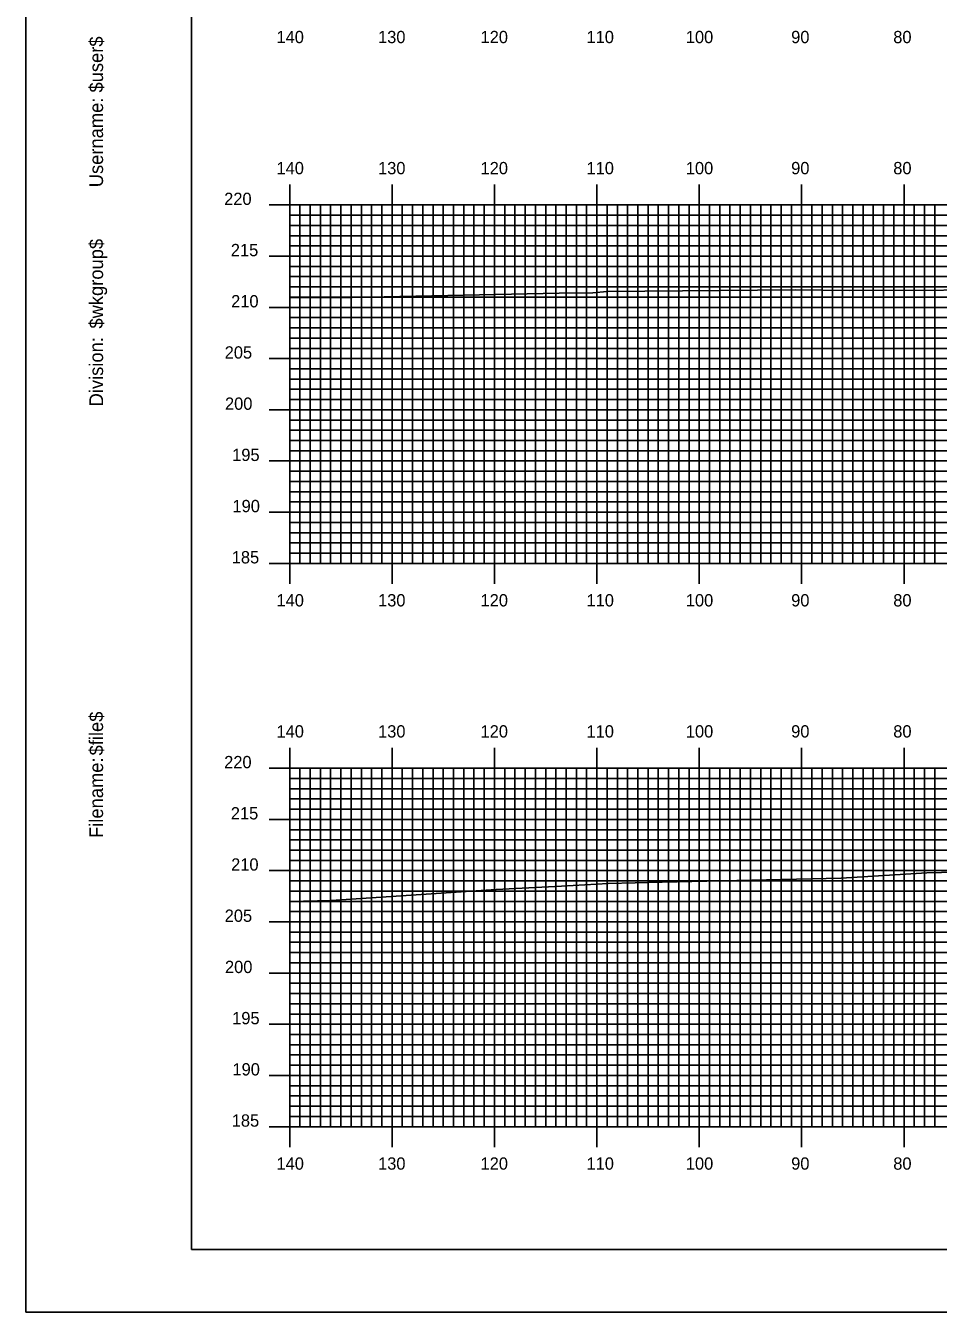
# Model space of a CAD drawing. Extents: x 1799962 to 1800305, y 442591 to 442811.
# Drawn here: x 1799961.7 to 1800050.9, y 442590.5 to 442716.2 of the extents above; entities that cross this region are included whole.
import ezdxf

# ---------------------------------------------------------------- set-up
doc = ezdxf.new("R2010")
doc.units = 0
for name, color, linetype in [('BORDER', 7, 'Continuous'), ('H_V ANNOTATION', 7, 'Continuous'), ('MAJOR', 7, 'Continuous'), ('MINOR', 7, 'Continuous'), ('PLOT BOUNDARY', 7, 'Continuous'), ('S_Roadway_Centerline', 7, 'Continuous')]:
    doc.layers.add(name, color=color, linetype=linetype)

msp = doc.modelspace()

# ---------------------------------------------------------------- linework, layer by layer
at = {"layer": 'BORDER'}
msp.add_lwpolyline([(1799977.92, 442596.67), (1800297.92, 442596.67), (1800297.92, 442806.67), (1799977.92, 442806.67)], close=True, dxfattribs=at)
at = {"layer": 'MAJOR'}
for p, q in [((1799987.52, 442700.67), (1799987.52, 442698.67)), ((1799997.52, 442700.67), (1799997.52, 442698.67)), ((1800007.52, 442700.67), (1800007.52, 442698.67)), ((1800017.52, 442700.67), (1800017.52, 442698.67)), ((1800027.52, 442700.67), (1800027.52, 442698.67)), ((1800037.52, 442700.67), (1800037.52, 442698.67)), ((1800047.52, 442700.67), (1800047.52, 442698.67)), ((1799985.52, 442698.67), (1799987.52, 442698.67)), ((1799987.52, 442698.67), (1800267.52, 442698.67)), ((1799987.52, 442663.67), (1799987.52, 442698.67)), ((1799987.52, 442663.67), (1799987.52, 442698.67)), ((1799987.52, 442698.67), (1800267.52, 442698.67)), ((1799997.52, 442663.67), (1799997.52, 442698.67)), ((1800007.52, 442663.67), (1800007.52, 442698.67)), ((1800017.52, 442663.67), (1800017.52, 442698.67)), ((1800027.52, 442663.67), (1800027.52, 442698.67)), ((1800037.52, 442663.67), (1800037.52, 442698.67)), ((1800047.52, 442663.67), (1800047.52, 442698.67)), ((1799985.52, 442693.67), (1799987.52, 442693.67)), ((1799987.52, 442693.67), (1800267.52, 442693.67)), ((1799985.52, 442688.67), (1799987.52, 442688.67)), ((1799987.52, 442688.67), (1800267.52, 442688.67)), ((1799985.52, 442683.67), (1799987.52, 442683.67)), ((1799987.52, 442683.67), (1800267.52, 442683.67)), ((1799985.52, 442678.67), (1799987.52, 442678.67)), ((1799987.52, 442678.67), (1800267.52, 442678.67)), ((1799985.52, 442673.67), (1799987.52, 442673.67)), ((1799987.52, 442673.67), (1800267.52, 442673.67)), ((1799985.52, 442668.67), (1799987.52, 442668.67)), ((1799987.52, 442668.67), (1800267.52, 442668.67)), ((1799985.52, 442663.67), (1799987.52, 442663.67)), ((1799987.52, 442663.67), (1800267.52, 442663.67)), ((1799987.52, 442663.67), (1800267.52, 442663.67)), ((1799987.52, 442661.66), (1799987.52, 442663.67)), ((1799997.52, 442661.66), (1799997.52, 442663.67)), ((1800007.52, 442661.66), (1800007.52, 442663.67)), ((1800017.52, 442661.66), (1800017.52, 442663.67)), ((1800027.52, 442661.66), (1800027.52, 442663.67)), ((1800037.52, 442661.66), (1800037.52, 442663.67)), ((1800047.52, 442661.66), (1800047.52, 442663.67)), ((1799987.52, 442645.67), (1799987.52, 442643.67)), ((1799997.52, 442645.67), (1799997.52, 442643.67)), ((1800007.52, 442645.67), (1800007.52, 442643.67)), ((1800017.52, 442645.67), (1800017.52, 442643.67)), ((1800027.52, 442645.67), (1800027.52, 442643.67)), ((1800037.52, 442645.67), (1800037.52, 442643.67)), ((1800047.52, 442645.67), (1800047.52, 442643.67)), ((1799985.52, 442643.67), (1799987.52, 442643.67)), ((1799987.52, 442643.67), (1800267.52, 442643.67)), ((1799987.52, 442608.67), (1799987.52, 442643.67)), ((1799987.52, 442608.67), (1799987.52, 442643.67)), ((1799987.52, 442643.67), (1800267.52, 442643.67)), ((1799997.52, 442608.67), (1799997.52, 442643.67)), ((1800007.52, 442608.67), (1800007.52, 442643.67)), ((1800017.52, 442608.67), (1800017.52, 442643.67)), ((1800027.52, 442608.67), (1800027.52, 442643.67)), ((1800037.52, 442608.67), (1800037.52, 442643.67)), ((1800047.52, 442608.67), (1800047.52, 442643.67)), ((1799985.52, 442638.67), (1799987.52, 442638.67)), ((1799987.52, 442638.67), (1800267.52, 442638.67)), ((1799985.52, 442633.67), (1799987.52, 442633.67)), ((1799987.52, 442633.67), (1800267.52, 442633.67)), ((1799985.52, 442628.67), (1799987.52, 442628.67)), ((1799987.52, 442628.67), (1800267.52, 442628.67)), ((1799985.52, 442623.67), (1799987.52, 442623.67)), ((1799987.52, 442623.67), (1800267.52, 442623.67)), ((1799985.52, 442618.67), (1799987.52, 442618.67)), ((1799987.52, 442618.67), (1800267.52, 442618.67)), ((1799985.52, 442613.67), (1799987.52, 442613.67)), ((1799987.52, 442613.67), (1800267.52, 442613.67)), ((1799985.52, 442608.67), (1799987.52, 442608.67)), ((1799987.52, 442608.67), (1800267.52, 442608.67)), ((1799987.52, 442608.67), (1800267.52, 442608.67)), ((1799987.52, 442606.66), (1799987.52, 442608.67)), ((1799997.52, 442606.66), (1799997.52, 442608.67)), ((1800007.52, 442606.66), (1800007.52, 442608.67)), ((1800017.52, 442606.66), (1800017.52, 442608.67)), ((1800027.52, 442606.66), (1800027.52, 442608.67)), ((1800037.52, 442606.66), (1800037.52, 442608.67)), ((1800047.52, 442606.66), (1800047.52, 442608.67))]:
    msp.add_line(p, q, dxfattribs=at)
at = {"layer": 'MINOR'}
for p, q in [((1799988.52, 442663.67), (1799988.52, 442698.67)), ((1799989.52, 442663.67), (1799989.52, 442698.67)), ((1799990.52, 442663.67), (1799990.52, 442698.67)), ((1799991.52, 442663.67), (1799991.52, 442698.67)), ((1799992.52, 442663.67), (1799992.52, 442698.67)), ((1799993.52, 442663.67), (1799993.52, 442698.67)), ((1799994.52, 442663.67), (1799994.52, 442698.67)), ((1799995.52, 442663.67), (1799995.52, 442698.67)), ((1799996.52, 442663.67), (1799996.52, 442698.67)), ((1799998.52, 442663.67), (1799998.52, 442698.67)), ((1799999.52, 442663.67), (1799999.52, 442698.67)), ((1800000.52, 442663.67), (1800000.52, 442698.67)), ((1800001.52, 442663.67), (1800001.52, 442698.67)), ((1800002.52, 442663.67), (1800002.52, 442698.67)), ((1800003.52, 442663.67), (1800003.52, 442698.67)), ((1800004.52, 442663.67), (1800004.52, 442698.67)), ((1800005.52, 442663.67), (1800005.52, 442698.67)), ((1800006.52, 442663.67), (1800006.52, 442698.67)), ((1800008.52, 442663.67), (1800008.52, 442698.67)), ((1800009.52, 442663.67), (1800009.52, 442698.67)), ((1800010.52, 442663.67), (1800010.52, 442698.67)), ((1800011.52, 442663.67), (1800011.52, 442698.67)), ((1800012.52, 442663.67), (1800012.52, 442698.67)), ((1800013.52, 442663.67), (1800013.52, 442698.67)), ((1800014.52, 442663.67), (1800014.52, 442698.67)), ((1800015.52, 442663.67), (1800015.52, 442698.67)), ((1800016.52, 442663.67), (1800016.52, 442698.67)), ((1800018.52, 442663.67), (1800018.52, 442698.67)), ((1800019.52, 442663.67), (1800019.52, 442698.67)), ((1800020.52, 442663.67), (1800020.52, 442698.67)), ((1800021.52, 442663.67), (1800021.52, 442698.67)), ((1800022.52, 442663.67), (1800022.52, 442698.67)), ((1800023.52, 442663.67), (1800023.52, 442698.67)), ((1800024.52, 442663.67), (1800024.52, 442698.67)), ((1800025.52, 442663.67), (1800025.52, 442698.67)), ((1800026.52, 442663.67), (1800026.52, 442698.67)), ((1800028.52, 442663.67), (1800028.52, 442698.67)), ((1800029.52, 442663.67), (1800029.52, 442698.67)), ((1800030.52, 442663.67), (1800030.52, 442698.67)), ((1800031.52, 442663.67), (1800031.52, 442698.67)), ((1800032.52, 442663.67), (1800032.52, 442698.67)), ((1800033.52, 442663.67), (1800033.52, 442698.67)), ((1800034.52, 442663.67), (1800034.52, 442698.67)), ((1800035.52, 442663.67), (1800035.52, 442698.67)), ((1800036.52, 442663.67), (1800036.52, 442698.67)), ((1800038.52, 442663.67), (1800038.52, 442698.67)), ((1800039.52, 442663.67), (1800039.52, 442698.67)), ((1800040.52, 442663.67), (1800040.52, 442698.67)), ((1800041.52, 442663.67), (1800041.52, 442698.67)), ((1800042.52, 442663.67), (1800042.52, 442698.67)), ((1800043.52, 442663.67), (1800043.52, 442698.67)), ((1800044.52, 442663.67), (1800044.52, 442698.67)), ((1800045.52, 442663.67), (1800045.52, 442698.67)), ((1800046.52, 442663.67), (1800046.52, 442698.67)), ((1800048.52, 442663.67), (1800048.52, 442698.67)), ((1800049.52, 442663.67), (1800049.52, 442698.67)), ((1800050.52, 442663.67), (1800050.52, 442698.67)), ((1799987.52, 442697.67), (1800267.52, 442697.67)), ((1799987.52, 442697.67), (1799989.53, 442697.67)), ((1799987.52, 442696.67), (1800267.52, 442696.67)), ((1799987.52, 442696.67), (1799989.53, 442696.67)), ((1799987.52, 442695.67), (1800267.52, 442695.67)), ((1799987.52, 442695.67), (1799989.53, 442695.67)), ((1799987.52, 442694.67), (1800267.52, 442694.67)), ((1799987.52, 442694.67), (1799989.53, 442694.67)), ((1799987.52, 442692.67), (1800267.52, 442692.67)), ((1799987.52, 442692.67), (1799989.53, 442692.67)), ((1799987.52, 442691.67), (1800267.52, 442691.67)), ((1799987.52, 442691.67), (1799989.53, 442691.67)), ((1799987.52, 442690.67), (1800267.52, 442690.67)), ((1799987.52, 442690.67), (1799989.53, 442690.67)), ((1799987.52, 442689.67), (1800267.52, 442689.67)), ((1799987.52, 442689.67), (1799989.53, 442689.67)), ((1799987.52, 442687.67), (1800267.52, 442687.67)), ((1799987.52, 442687.67), (1799989.53, 442687.67)), ((1799987.52, 442686.67), (1800267.52, 442686.67)), ((1799987.52, 442686.67), (1799989.53, 442686.67)), ((1799987.52, 442685.67), (1800267.52, 442685.67)), ((1799987.52, 442685.67), (1799989.53, 442685.67)), ((1799987.52, 442684.67), (1800267.52, 442684.67)), ((1799987.52, 442684.67), (1799989.53, 442684.67)), ((1799987.52, 442682.67), (1800267.52, 442682.67)), ((1799987.52, 442682.67), (1799989.53, 442682.67)), ((1799987.52, 442681.67), (1800267.52, 442681.67)), ((1799987.52, 442681.67), (1799989.53, 442681.67)), ((1799987.52, 442680.67), (1800267.52, 442680.67)), ((1799987.52, 442680.67), (1799989.53, 442680.67)), ((1799987.52, 442679.67), (1800267.52, 442679.67)), ((1799987.52, 442679.67), (1799989.53, 442679.67)), ((1799987.52, 442677.67), (1800267.52, 442677.67)), ((1799987.52, 442677.67), (1799989.53, 442677.67)), ((1799987.52, 442676.67), (1800267.52, 442676.67)), ((1799987.52, 442676.67), (1799989.53, 442676.67)), ((1799987.52, 442675.67), (1800267.52, 442675.67)), ((1799987.52, 442675.67), (1799989.53, 442675.67)), ((1799987.52, 442674.67), (1800267.52, 442674.67)), ((1799987.52, 442674.67), (1799989.53, 442674.67)), ((1799987.52, 442672.67), (1800267.52, 442672.67)), ((1799987.52, 442672.67), (1799989.53, 442672.67)), ((1799987.52, 442671.67), (1800267.52, 442671.67)), ((1799987.52, 442671.67), (1799989.53, 442671.67)), ((1799987.52, 442670.67), (1800267.52, 442670.67)), ((1799987.52, 442670.67), (1799989.53, 442670.67)), ((1799987.52, 442669.67), (1800267.52, 442669.67)), ((1799987.52, 442669.67), (1799989.53, 442669.67)), ((1799987.52, 442667.67), (1800267.52, 442667.67)), ((1799987.52, 442667.67), (1799989.53, 442667.67)), ((1799987.52, 442666.67), (1800267.52, 442666.67)), ((1799987.52, 442666.67), (1799989.53, 442666.67)), ((1799987.52, 442665.67), (1800267.52, 442665.67)), ((1799987.52, 442665.67), (1799989.53, 442665.67)), ((1799987.52, 442664.67), (1800267.52, 442664.67)), ((1799987.52, 442664.67), (1799989.53, 442664.67)), ((1799988.52, 442608.67), (1799988.52, 442643.67)), ((1799989.52, 442608.67), (1799989.52, 442643.67)), ((1799990.52, 442608.67), (1799990.52, 442643.67)), ((1799991.52, 442608.67), (1799991.52, 442643.67)), ((1799992.52, 442608.67), (1799992.52, 442643.67)), ((1799993.52, 442608.67), (1799993.52, 442643.67)), ((1799994.52, 442608.67), (1799994.52, 442643.67)), ((1799995.52, 442608.67), (1799995.52, 442643.67)), ((1799996.52, 442608.67), (1799996.52, 442643.67)), ((1799998.52, 442608.67), (1799998.52, 442643.67)), ((1799999.52, 442608.67), (1799999.52, 442643.67)), ((1800000.52, 442608.67), (1800000.52, 442643.67)), ((1800001.52, 442608.67), (1800001.52, 442643.67)), ((1800002.52, 442608.67), (1800002.52, 442643.67)), ((1800003.52, 442608.67), (1800003.52, 442643.67)), ((1800004.52, 442608.67), (1800004.52, 442643.67)), ((1800005.52, 442608.67), (1800005.52, 442643.67)), ((1800006.52, 442608.67), (1800006.52, 442643.67)), ((1800008.52, 442608.67), (1800008.52, 442643.67)), ((1800009.52, 442608.67), (1800009.52, 442643.67)), ((1800010.52, 442608.67), (1800010.52, 442643.67)), ((1800011.52, 442608.67), (1800011.52, 442643.67)), ((1800012.52, 442608.67), (1800012.52, 442643.67)), ((1800013.52, 442608.67), (1800013.52, 442643.67)), ((1800014.52, 442608.67), (1800014.52, 442643.67)), ((1800015.52, 442608.67), (1800015.52, 442643.67)), ((1800016.52, 442608.67), (1800016.52, 442643.67)), ((1800018.52, 442608.67), (1800018.52, 442643.67)), ((1800019.52, 442608.67), (1800019.52, 442643.67)), ((1800020.52, 442608.67), (1800020.52, 442643.67)), ((1800021.52, 442608.67), (1800021.52, 442643.67)), ((1800022.52, 442608.67), (1800022.52, 442643.67)), ((1800023.52, 442608.67), (1800023.52, 442643.67)), ((1800024.52, 442608.67), (1800024.52, 442643.67)), ((1800025.52, 442608.67), (1800025.52, 442643.67)), ((1800026.52, 442608.67), (1800026.52, 442643.67)), ((1800028.52, 442608.67), (1800028.52, 442643.67)), ((1800029.52, 442608.67), (1800029.52, 442643.67)), ((1800030.52, 442608.67), (1800030.52, 442643.67)), ((1800031.52, 442608.67), (1800031.52, 442643.67)), ((1800032.52, 442608.67), (1800032.52, 442643.67)), ((1800033.52, 442608.67), (1800033.52, 442643.67)), ((1800034.52, 442608.67), (1800034.52, 442643.67)), ((1800035.52, 442608.67), (1800035.52, 442643.67)), ((1800036.52, 442608.67), (1800036.52, 442643.67)), ((1800038.52, 442608.67), (1800038.52, 442643.67)), ((1800039.52, 442608.67), (1800039.52, 442643.67)), ((1800040.52, 442608.67), (1800040.52, 442643.67)), ((1800041.52, 442608.67), (1800041.52, 442643.67)), ((1800042.52, 442608.67), (1800042.52, 442643.67)), ((1800043.52, 442608.67), (1800043.52, 442643.67)), ((1800044.52, 442608.67), (1800044.52, 442643.67)), ((1800045.52, 442608.67), (1800045.52, 442643.67)), ((1800046.52, 442608.67), (1800046.52, 442643.67)), ((1800048.52, 442608.67), (1800048.52, 442643.67)), ((1800049.52, 442608.67), (1800049.52, 442643.67)), ((1800050.52, 442608.67), (1800050.52, 442643.67)), ((1799987.52, 442642.67), (1800267.52, 442642.67)), ((1799987.52, 442642.67), (1799989.53, 442642.67)), ((1799987.52, 442641.67), (1800267.52, 442641.67)), ((1799987.52, 442641.67), (1799989.53, 442641.67)), ((1799987.52, 442640.67), (1800267.52, 442640.67)), ((1799987.52, 442640.67), (1799989.53, 442640.67)), ((1799987.52, 442639.67), (1800267.52, 442639.67)), ((1799987.52, 442639.67), (1799989.53, 442639.67)), ((1799987.52, 442637.67), (1800267.52, 442637.67)), ((1799987.52, 442637.67), (1799989.53, 442637.67)), ((1799987.52, 442636.67), (1800267.52, 442636.67)), ((1799987.52, 442636.67), (1799989.53, 442636.67)), ((1799987.52, 442635.67), (1800267.52, 442635.67)), ((1799987.52, 442635.67), (1799989.53, 442635.67)), ((1799987.52, 442634.67), (1800267.52, 442634.67)), ((1799987.52, 442634.67), (1799989.53, 442634.67)), ((1799987.52, 442632.67), (1800267.52, 442632.67)), ((1799987.52, 442632.67), (1799989.53, 442632.67)), ((1799987.52, 442631.67), (1800267.52, 442631.67)), ((1799987.52, 442631.67), (1799989.53, 442631.67)), ((1799987.52, 442630.67), (1800267.52, 442630.67)), ((1799987.52, 442630.67), (1799989.53, 442630.67)), ((1799987.52, 442629.67), (1800267.52, 442629.67)), ((1799987.52, 442629.67), (1799989.53, 442629.67)), ((1799987.52, 442627.67), (1800267.52, 442627.67)), ((1799987.52, 442627.67), (1799989.53, 442627.67)), ((1799987.52, 442626.67), (1800267.52, 442626.67)), ((1799987.52, 442626.67), (1799989.53, 442626.67)), ((1799987.52, 442625.67), (1800267.52, 442625.67)), ((1799987.52, 442625.67), (1799989.53, 442625.67)), ((1799987.52, 442624.67), (1800267.52, 442624.67)), ((1799987.52, 442624.67), (1799989.53, 442624.67)), ((1799987.52, 442622.67), (1800267.52, 442622.67)), ((1799987.52, 442622.67), (1799989.53, 442622.67)), ((1799987.52, 442621.67), (1800267.52, 442621.67)), ((1799987.52, 442621.67), (1799989.53, 442621.67)), ((1799987.52, 442620.67), (1800267.52, 442620.67)), ((1799987.52, 442620.67), (1799989.53, 442620.67)), ((1799987.52, 442619.67), (1800267.52, 442619.67)), ((1799987.52, 442619.67), (1799989.53, 442619.67)), ((1799987.52, 442617.67), (1800267.52, 442617.67)), ((1799987.52, 442617.67), (1799989.53, 442617.67)), ((1799987.52, 442616.67), (1800267.52, 442616.67)), ((1799987.52, 442616.67), (1799989.53, 442616.67)), ((1799987.52, 442615.67), (1800267.52, 442615.67)), ((1799987.52, 442615.67), (1799989.53, 442615.67)), ((1799987.52, 442614.67), (1800267.52, 442614.67)), ((1799987.52, 442614.67), (1799989.53, 442614.67)), ((1799987.52, 442612.67), (1800267.52, 442612.67)), ((1799987.52, 442612.67), (1799989.53, 442612.67)), ((1799987.52, 442611.67), (1800267.52, 442611.67)), ((1799987.52, 442611.67), (1799989.53, 442611.67)), ((1799987.52, 442610.67), (1800267.52, 442610.67)), ((1799987.52, 442610.67), (1799989.53, 442610.67)), ((1799987.52, 442609.67), (1800267.52, 442609.67)), ((1799987.52, 442609.67), (1799989.53, 442609.67))]:
    msp.add_line(p, q, dxfattribs=at)
at = {"layer": 'PLOT BOUNDARY'}
msp.add_lwpolyline([(1799961.74, 442590.55), (1800301.74, 442590.55), (1800301.74, 442810.55), (1799961.74, 442810.55)], close=True, dxfattribs=at)
at = {"layer": 'S_Roadway_Centerline'}
for points in [[(1799987.52, 442689.6), (1799993.61, 442689.62), (1800013.84, 442690.07), (1800017.14, 442690.1), (1800018.53, 442690.21), (1800036.88, 442690.37), (1800042.19, 442690.31), (1800060.6, 442690.39), (1800064.16, 442690.4), (1800068.01, 442690.34), (1800092.68, 442690.26), (1800105.22, 442690.02), (1800110.64, 442689.98), (1800115.31, 442690.13), (1800127.86, 442690.02), (1800139.25, 442689.77), (1800144.2, 442689.77), (1800163.19, 442690.31)], [(1799987.52, 442630.67), (1799991.56, 442630.77), (1800007.69, 442631.83), (1800014.08, 442632.16), (1800018.63, 442632.4), (1800023.9, 442632.56), (1800041.39, 442632.95), (1800049.75, 442633.44), (1800054.08, 442633.55), (1800057.92, 442633.59), (1800071.67, 442633.71), (1800080.81, 442633.72), (1800096.35, 442633.61), (1800103.47, 442633.65), (1800120.62, 442633.63), (1800124.86, 442633.46), (1800145.55, 442633.91), (1800146.28, 442633.97), (1800147.08, 442633.93), (1800157.96, 442633.42), (1800167.23, 442633.22)]]:
    msp.add_lwpolyline(points, dxfattribs=at)

# ---------------------------------------------------------------- texts
at = {"layer": 'BORDER'}
for s, p in [('$user$', (1799969.29, 442709.65)), ('Username:', (1799969.29, 442700.4)), ('$wkgroup$', (1799969.29, 442686.6)), ('Division:', (1799969.29, 442679)), ('$file$', (1799969.29, 442644.92)), ('Filename:', (1799969.29, 442636.86))]:
    msp.add_text(s, height=1.339, rotation=90, dxfattribs=at).set_placement(p)
at = {"layer": 'H_V ANNOTATION'}
for s, p in [('140', (1799986.23, 442714.47)), ('130', (1799996.15, 442714.47)), ('120', (1800006.16, 442714.47)), ('110', (1800016.51, 442714.47)), ('100', (1800026.21, 442714.47)), ('90', (1800036.5, 442714.47)), ('80', (1800046.47, 442714.47)), ('140', (1799986.23, 442701.67)), ('130', (1799996.15, 442701.67)), ('120', (1800006.16, 442701.67)), ('110', (1800016.51, 442701.67)), ('100', (1800026.21, 442701.67)), ('90', (1800036.5, 442701.67)), ('80', (1800046.47, 442701.67)), ('220', (1799981.12, 442698.67)), ('215', (1799981.77, 442693.67)), ('210', (1799981.8, 442688.67)), ('205', (1799981.17, 442683.67)), ('200', (1799981.2, 442678.67)), ('195', (1799981.9, 442673.67)), ('190', (1799981.93, 442668.67)), ('185', (1799981.86, 442663.67)), ('140', (1799986.23, 442659.47)), ('130', (1799996.15, 442659.47)), ('120', (1800006.16, 442659.47)), ('110', (1800016.51, 442659.47)), ('100', (1800026.21, 442659.47)), ('90', (1800036.5, 442659.47)), ('80', (1800046.47, 442659.47)), ('140', (1799986.23, 442646.67)), ('130', (1799996.15, 442646.67)), ('120', (1800006.16, 442646.67)), ('110', (1800016.51, 442646.67)), ('100', (1800026.21, 442646.67)), ('90', (1800036.5, 442646.67)), ('80', (1800046.47, 442646.67)), ('220', (1799981.12, 442643.67)), ('215', (1799981.77, 442638.67)), ('210', (1799981.8, 442633.67)), ('205', (1799981.17, 442628.67)), ('200', (1799981.2, 442623.67)), ('195', (1799981.9, 442618.67)), ('190', (1799981.93, 442613.67)), ('185', (1799981.86, 442608.67)), ('140', (1799986.23, 442604.47)), ('130', (1799996.15, 442604.47)), ('120', (1800006.16, 442604.47)), ('110', (1800016.51, 442604.47)), ('100', (1800026.21, 442604.47)), ('90', (1800036.5, 442604.47)), ('80', (1800046.47, 442604.47))]:
    msp.add_text(s, height=1.2, dxfattribs=at).set_placement(p)
at = {"layer": 'MAJOR'}
for p in [(1799987.51, 442663.67), (1799987.51, 442608.67)]:
    msp.add_text('-', height=0.012, dxfattribs=at).set_placement(p)

doc.saveas('drawing.dxf')
